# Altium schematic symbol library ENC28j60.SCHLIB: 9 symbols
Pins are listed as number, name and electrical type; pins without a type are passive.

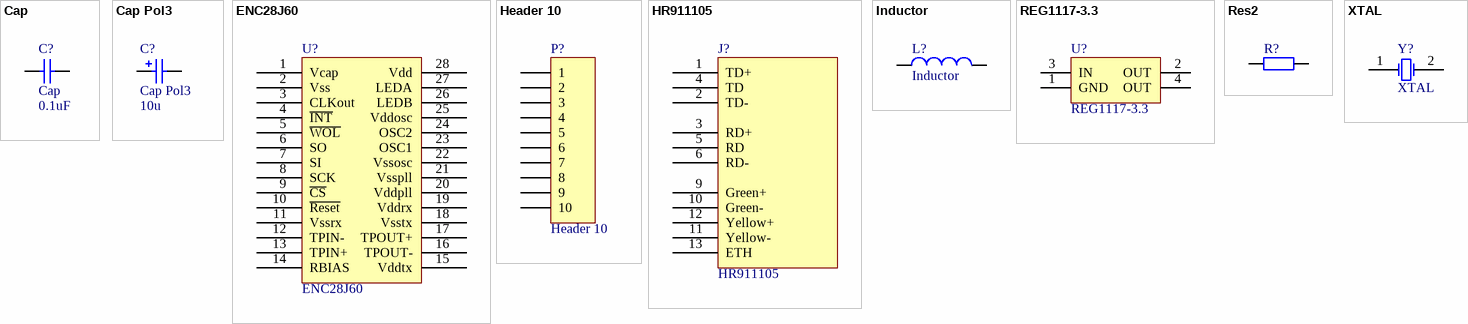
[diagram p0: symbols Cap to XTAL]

## Cap
designator C?  value 0.1uF
Capacitor
footprint RAD-0.3 (Capacitor; 2 Leads)
footprint VP32-3.2 (Capacitor, Ceramic, Thru-Hole, Dipped Radial; Body 5.1 x 3.2 mm (WxT) Pin Spacing 2.54 mm (typ))
footprint VP45-3.2 (Capacitor, Ceramic, Thru-Hole, Dipped Radial; Body 7.8 x 3.2 mm (WxT) Pin Spacing 5.08 mm (typ))
simulation model CAP (Capacitor)
signal-integrity model Cap
footprint C1206 (Chip Capacitor; Body 3.2 x 1.6 mm (LxW typ))
footprint 0805
footprint 0803
footprint C0805
pins: 1, 2

## Cap Pol3
designator C?  value 10u
Polarized Capacitor (Surface Mount)
footprint C0805 (Chip Capacitor; Body 2.0 x 1.2 mm (LxW typ))
footprint 1812 (Chip Capacitor; Body 4.5 x 3.2 mm (LxW typ))
footprint 1825 (Chip Capacitor; Body 4.5 x 6.4 mm (LxW typ))
footprint C2225 (Chip Capacitor; Body 5.6 x 6.4 mm (LxW typ))
footprint 2220 (Chip Capacitor; Body 5.7 x 5.0 mm (LxW typ))
simulation model CAP (Capacitor)
signal-integrity model Cap Pol
pins: 1, 2
1 alternate drawing of the same symbol

## ENC28J60
designator U?
footprint DIP-28 (DIP; 28 Leads; Row Spacing 7.62 mm; Pitch 2.54 mm)
footprint DIP28
pins: 1 Vcap, 2 Vss, 3 CLKout, 4 ~{INT}, 5 ~{WOL}, 6 SO, 7 SI, 8 SCK, 9 ~{CS}, 10 ~{Reset}, 11 Vssrx, 12 TPIN-, 13 TPIN+, 14 RBIAS, 15 Vddtx, 16 TPOUT-, 17 TPOUT+, 18 Vsstx, 19 Vddrx, 20 Vddpll, 21 Vsspll, 22 Vssosc, 23 OSC1, 24 OSC2, 25 Vddosc, 26 LEDB, 27 LEDA, 28 Vdd

## Header 10
designator P?
Header, 10-Pin
footprint HDR1X10 (Connector; Header; 10 Position)
signal-integrity model Connector
pins: 1, 2, 3, 4, 5, 6, 7, 8, 9, 10

## HR911105
designator J?
footprint HR911105A (HR911105A 带网络变压器及LED的一体化RJ45插座)
pins: 1 TD+, 2 TD-, 3 RD+, 4 TD, 5 RD, 6 RD-, 9 Green+, 10 Green-, 11 Yellow-, 12 Yellow+, 13 ETH

## Inductor
designator L?
Code_IEC: 1005; Value: 10mH
simulation model INDUCTOR (Inductor)
signal-integrity model Inductor
footprint AXIAL-0.5 (Semiconductor Resistor; 2 Leads)
pins: 1, 2

## REG1117-3.3
designator U?
800mA and 1A Low Dropout Positive Regulator 2.85V, 3.3V, 5V, and Adjustable
footprint ZZ311 (SOT-223/SC-73; 4 Leads; Body 6.7 x 7.3 mm, inc. leads (LxW max))
pins: 1 GND (power), 2 OUT (power), 3 IN (power), 4 OUT (power)

## Res2
designator R?  (value not drawn)
Resistor; Value: 10K
footprint AXIAL-0.4 (Resistor; 2 Leads)
simulation model RESISTOR (Resistor)
signal-integrity model Res
footprint 1206
footprint 0805
footprint C0805
pins: 1, 2

## XTAL
designator Y?
Crystal Oscillator
footprint R38 (Crystal, Thru-Hole; 2 Leads; Body 3.1 x 8.2 mm (Dia.xH))
simulation model XTAL (Spice Subcircuit)
footprint XTAL (晶振)
pins: 1 OSC1, 2 OSC2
